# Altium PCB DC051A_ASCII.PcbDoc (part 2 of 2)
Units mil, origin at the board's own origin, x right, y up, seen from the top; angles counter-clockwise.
Board outline 3200 x 2600 mil, 4 copper layers (L1-TOP, L2-GND, L3-POWER, L4-BOTTOM), stack 58.217 mil thick; 95 components, 55 nets, 249 pads, 164 vias.
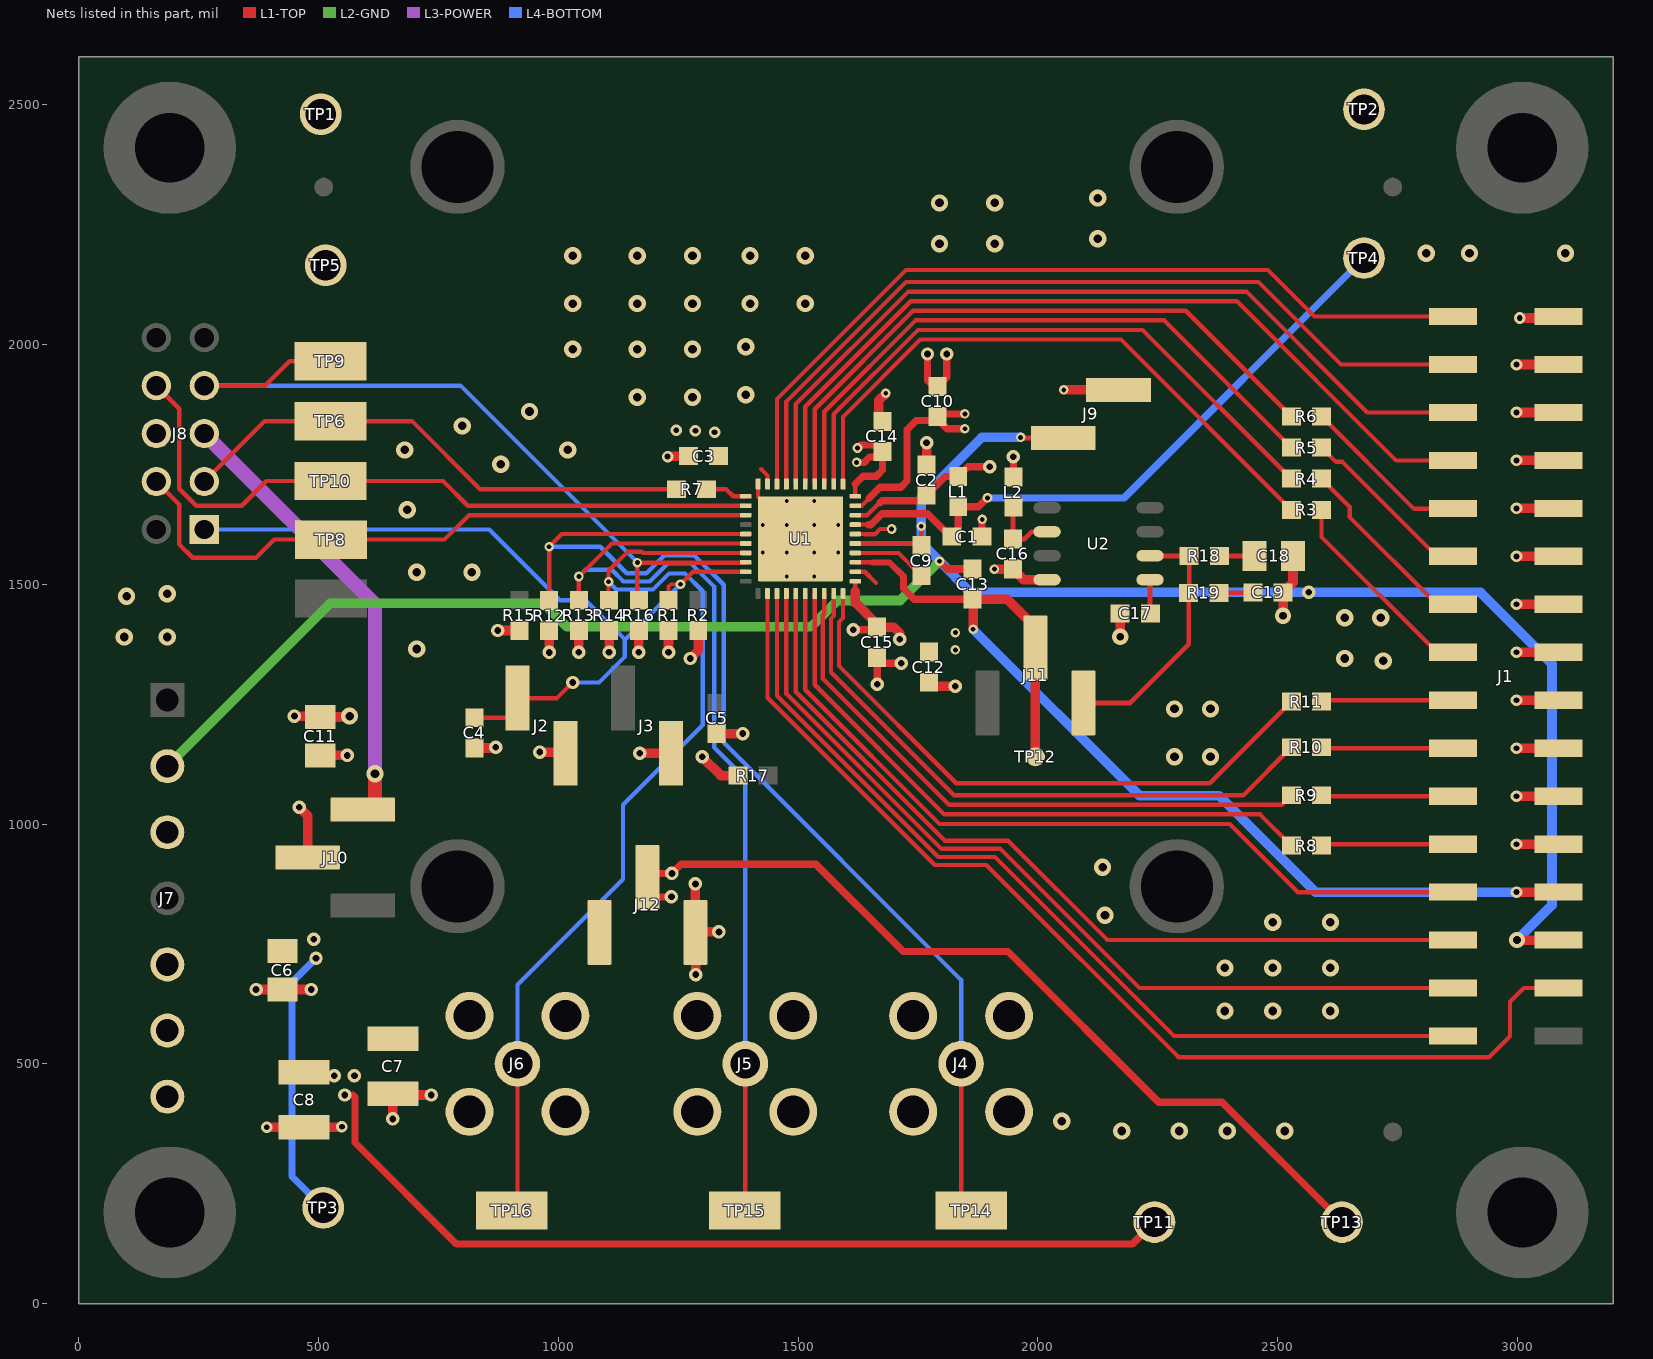
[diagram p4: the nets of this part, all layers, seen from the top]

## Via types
v1: diameter 36, hole 18, L1-TOP to L4-BOTTOM, tented both sides, 64 vias
v2: diameter 28, hole 14, L1-TOP to L4-BOTTOM, tented both sides, 41 vias
v3: diameter 20, hole 10, L1-TOP to L4-BOTTOM, tented both sides, 25 vias
v4: diameter 24, hole 12, L1-TOP to L4-BOTTOM, tented both sides, 19 vias
v5: diameter 19.68, hole 7.87, L1-TOP to L4-BOTTOM, 12 vias
v6: diameter 34, hole 16, L1-TOP to L4-BOTTOM, 3 vias

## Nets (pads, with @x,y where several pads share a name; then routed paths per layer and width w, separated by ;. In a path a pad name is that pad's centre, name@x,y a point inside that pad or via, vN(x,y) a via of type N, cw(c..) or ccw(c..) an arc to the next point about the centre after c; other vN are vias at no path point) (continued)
GND: C1.2 C2.2 C3.2 C4.2 C5.2 C6.2 C7.2 C8.2 C10.2 C11.2 C12.2 C14.2 C15.2 C16.2 C17.2 C18.2 C19.2 J1.9 J1.11 J1.13 J1.15 J1.17 J1.19 J1.21 J1.23 J1.25 J1.27 J1.29 J1.31 J2.1 J3.1 J4.2 J4.3 J4.4 J4.5 J5.2 J5.3 J5.4 J5.5 J6.2 J6.3 J6.4 J6.5 J7.3 J8.6 J9.1 J12.1 TP1.1 TP2.1 U1.10 U1.36 U1.41@1505.28,1594.7 U2.4 | length 3247.9
  L1-TOP w9: U1.10@1416.69,1708.88 1416.69,1683.28 U1.41@1505.28,1594.7 ; U1.36@1619.45,1604.54 1638.39,1604.54 1638.77,1604.17 1660.27,1604.17 1671.11,1615 v3(1695,1615)
  L1-TOP w10: J1.31@3054,2058 J1.31@3086,2058
  L1-TOP w15: v2(1665,1291.5) 1665,1339 1669,1335 v2(1715,1335) ; v2(1770,1980) 1770,1925 1782.5,1912.5 1786.75,1916.75 1791,1921 1800,1921 1810,1931 v2(1810,1980) ; C1.2@1883.5,1599 v3@1883.5,1637.5
  L1-TOP w20: v2(370,655) C6.2@425,655 v2(485,655) ; v4(392.09,367.91) C8.2@470,367.91 547.91,367.91 v4(548.96,368.96) ; v2(450,1225) 501,1225 C11.2@503,1223 ; C11.2@504,1223 563,1223 v1(565,1225) ; v2(655,385) C7.2@655,437.91 657.91,435 v2(735,435) ; C4.2@825,1158.5 873.5,1158.5 872.01,1160 v2(870,1160) ; v2@960,1150 v2(961.5,1150) J2.1@1030,1150 ; v2(1170,1147.52) J3.1@1235,1147.52 ; v4(1228,1766) 1229,1767 C3.2@1271.5,1767 ; v2(1286,875) J12.1@1286,774.02 ; v2(1287,686) 1287,710 1277,720 1286,729 J12.1@1286,774.02 ; C5.2@1322.5,1185 C5.2@1330,1185 ; C5.2@1330,1188.5 v2(1385,1188.5) ; v2(1335,775) 1287,775 J12.1@1286,774.02 ; C14.2@1668,1849 1668,1883 v3(1683,1898) ; C2.2@1768,1748.5 v2(1768,1795) ; C12.2@1773,1287 v2(1828,1287) ; v3(1909.5,1531.5) C16.2@1948,1531.5 1970.16,1509.34 U2.4@2019.36,1509.34 ; v3(2054,1905) J9.1@2168,1905 ; v6(2171.5,1390.5) C17.2@2171.5,1439 ; v6(2511,1434) 2511.5,1434.5 C19.2@2511.5,1483 2532,1503.5 C18.2@2532,1559 ; v4(2998,958) J1.9@3086,958 ; v4(2998,1058) J1.11@3086,1058 ; v4(2998,1158) J1.13@3086,1158 ; v4(2998,1258) J1.15@3086,1258 ; v4(2998,1358) J1.17@3086,1358 ; v4(2998,1458) J1.19@3086,1458 ; v4(2998,1558) J1.21@3086,1558 ; v4(2998,1658) J1.23@3086,1658 ; v4(2998,1758) J1.25@3086,1758 ; v4(2998,1858) J1.27@3086,1858 ; v4(2998,1958) J1.29@3086,1958 ; v4(3005,2055) J1.31@3093,2055
  other v1: 2175,360 2295,360 2395,360 2515,360 2050,380 2390,610 2490,610 2610,610 2390,700 2490,700 2610,700 2490,795 2610,795 2140,810 2135,910 2285,1140 2360,1140 2285,1240 2360,1240 2720,1340 2640,1345 705,1365 95,1390 185,1390 2640,1430 2715,1430 100,1475 185,1480 705,1525 820,1525 685,1655 880,1750 680,1780 1020,1780 800,1830 940,1860 1165,1890 1280,1890 1391.1,1895 1030,1990 1165,1990 1280,1990 1391.1,1995 1030,2085 1165,2085 1280,2085 1400,2085 1515,2085 1030,2185 1165,2185 1280,2185 1400,2185 1515,2185 2810,2190 2900,2190 3100,2190 1795,2210 1910,2210 2125,2220 1795,2295 1910,2295 2125,2305
  other v3: 1884,1635
  other v5: 1476.54,1515.96 1534.02,1515.96 1426.54,1565.96 1476.54,1565.96 1534.02,1565.96 1584.02,1565.96 1426.54,1623.44 1476.54,1623.44 1534.02,1623.44 1584.02,1623.44 1476.54,1673.44 1534.02,1673.44
LDAC_GPIO3: J8.7 R16.2 TP9.1 U1.18 | length 1650.6
  L1-TOP w9: J8.7@262,1914 389,1914 440,1965 TP9.1@525,1965 ; R16.2@1168,1466.5 1173.49,1471.99 1165,1480.47 v3(1165,1545) 1390.62,1545 U1.18@1391.1,1545.49
  L4-BOTTOM w9: J8.7@262,1914 796,1914 v3(1165,1545)
MISO_RXD: J8.3 R7.1 TP6.1 | length 1095.5
  L1-TOP w9: J8.3@262,1714 388,1840 TP6.1@525,1840 695,1840 837,1698 R7.1@1246.5,1698
MOSI_TXD: J8.4 TP8.1 U1.13 | length 1380.4
  L1-TOP w9: J8.4@162,1714 210,1666 210,1583 238,1555 370,1555 408,1593 TP8.1@526,1593 763,1593 813.91,1643.91 U1.13@1391.1,1643.91
NetC1_1: C1.1 L1.2 TP4.1 U1.37 | length 1359.3
  L1-TOP w8: U1.37@1619.45,1624.23 1647,1624.23
  L1-TOP w15: 1647,1624.04 1652.04,1624.04 1675,1647 1770,1647 1814.25,1602.75 1816.75,1602.75 C1.1@1820.5,1599 1820.5,1603.5 1834,1617 L1.2@1834,1661.5 1876.5,1661.5 v3(1895,1680)
  L4-BOTTOM w15: v3(1895,1680) 2180,1680 TP4.1@2680,2180
NetC9_1: C9.1 U1.34 | length 157.3
  L1-TOP w9: U1.34@1619.45,1565.17 1709.33,1565.17 C9.1@1757,1517.5
NetC10_1: C10.1 C12.1 J12.2 TP13.1 U1.32 U1.39 | length 2343.4
  L1-TOP w9: U1.32@1619.45,1525.8 1639.2,1525.8 1662.5,1502.5 ; U1.39@1619.45,1663.6 1632.6,1663.6 1634.99,1665.99 1635.23,1665.99 1643.64,1674.39 1643.64,1674.64 1648,1679
  L1-TOP w15: J12.2@1186,934 J12.2@1186,888.98 1194.02,897 v2(1237,897) 1256,916 1537.15,916 1719.15,734 1938,734 2252,420 2384,420 TP13.1@2634,170 ; J12.2@1193.02,848.02 v2(1236,848.02) ; 1648,1679.35 1670.65,1702 1714,1702 1727,1715 1727,1822 1746,1841 C10.1@1791,1841 ; v3(1848,1824) 1811,1824 1794,1841 C10.1@1791,1841 ; v3(1848,1855) 1805,1855 C10.1@1791,1841
  other v3: 1828,1363 1828,1399
NetC16_1: C16.1 L2.2 U2.2 | length 143.9
  L1-TOP w10: L2.2@1949,1660.5 1948,1659.5 C16.1@1948,1594.5 1972.76,1594.5 1987.61,1609.34 U2.2@2019.36,1609.34
NetC17_1: C17.1 U2.5 | length 70.6
  L1-TOP w10: U2.5@2233.93,1509.34 2233.93,1439.56 C17.1@2234.5,1439
NetC18_1: C18.1 R18.1 | length 73.5
  L1-TOP w10: R18.1@2378.5,1559 C18.1@2452,1559
NetC19_1: C19.1 R19.1 | length 71.4
  L1-TOP w10: R19.1@2377.5,1482 2447.5,1482 C19.1@2448.5,1483
NetJ1_3: J1.3 U1.22 | length 2279.1
  L1-TOP w9: U1.22@1436.38,1480.53 1436.38,1263.17 1785.17,914.38 1892.62,914.38 2293,514 2941,514 2984.5,557.5 2984.5,629.5 3013,658 J1.3@3086,658
NetJ4_1: J4.1 R12.2 TP14.1 U1.15 | length 2488.7
  L1-TOP w8: R12.2@981,1484 R12.2@986,1479
  L1-TOP w9: R12.2@981,1466 981,1484 v3(981,1578) 1007.54,1604.54 U1.15@1391.1,1604.54 ; J4.1@1840,500 1840,220 TP14.1@1866,194
  L4-BOTTOM w9: v3(981,1578) 1087.51,1578 1142.88,1522.63 1183.73,1522.63 1221.23,1560.12 1283.74,1560.12 1345,1498.86 1345,1170 1840,675 J4.1@1840,500
NetJ5_1: J5.1 R13.2 TP15.1 U1.16 | length 2087.8
  L1-TOP w9: R13.2@1043,1466.5 v3(1043,1516) 1111.86,1584.86 U1.16@1391.1,1584.86 ; TP15.1@1389,194 1389.99,194.99 J5.1@1389.99,500
  L4-BOTTOM w9: v3(1043,1516) 1057,1530 1111.64,1530 1135.89,1505.75 1190.72,1505.75 1228.22,1543.25 1276.75,1543.25 1325,1495 1325,1160 1390,1095 J5.1@1389.99,500
NetJ6_1: J6.1 R14.2 TP16.1 U1.17 | length 2062.5
  L1-TOP w8: v3(1105,1505) 1105,1473.5 1102,1470.5 R14.2@1106,1466.5
  L1-TOP w9: TP16.1@888,194 915,221 J6.1@915,500 ; v3(1105,1505) 1105,1527.99 1144.38,1567.37 1174.27,1567.37 1176.47,1565.17 U1.17@1391.1,1565.17
  L4-BOTTOM w9: J6.1@915,500 915,665 1135,885 1135,1040 1301.37,1206.37 1301.37,1485.27 1264.27,1522.37 1231.21,1522.37 1197.71,1488.88 1121.12,1488.88 v3(1105,1505)
NetJ11_1: J11.1 R18.2 R19.2 U2.6 | length 551.6
  L1-TOP w10: J11.1@2095,1252.52 2192.5,1252.5 2314.5,1374.5 R19.2@2314.5,1482 2315.5,1483 R18.2@2315.5,1559 2219.34,1559 U2.6@2219,1559.34
NetR3_1: R3.1 U1.1 | length 1288.4
  L1-TOP w9: U1.1@1593.86,1708.88 1593.86,1848.86 1755,2010 2173.5,2010 R3.1@2528.5,1655
NetR4_1: R4.1 U1.2 | length 1300.9
  L1-TOP w9: U1.2@1574.17,1708.88 1574.18,1854.18 1750,2030 2218.5,2030 R4.1@2528.5,1720
NetR5_1: R5.1 U1.3 | length 1313.3
  L1-TOP w9: U1.3@1554.49,1708.88 1554.49,1859.49 1745,2050 2263.5,2050 R5.1@2528.5,1785
NetR6_1: R6.1 U1.4 | length 1325.8
  L1-TOP w9: U1.4@1534.8,1708.88 1534.81,1864.81 1740,2070 2308.5,2070 R6.1@2528.5,1850
NetR7_2: R7.2 U1.11 | length 87.7
  L1-TOP w9: R7.2@1309.5,1698 1350,1698 1364.72,1683.28 U1.11@1391.1,1683.28
NetR8_1: R8.1 U1.27 | length 1322.9
  L1-TOP w9: U1.27@1534.8,1480.53 1534.81,1290.19 1805,1020 2463.5,1020 R8.1@2528.5,955
NetR9_1: R9.1 U1.28 | length 1272.6
  L1-TOP w9: U1.28@1554.49,1480.53 1554.49,1437.86 1551.68,1435.05 1551.68,1303.32 1815,1040 2508.5,1040 R9.1@2528.5,1060
NetR10_1: R10.1 U1.29 | length 1274
  L1-TOP w9: U1.29@1574.17,1480.53 1574.18,1433.68 1568.55,1428.06 1568.55,1316.45 1825,1060 2428.5,1060 R10.1@2528.5,1160
NetR11_1: R11.1 U1.30 | length 1269.2
  L1-TOP w9: U1.30@1593.86,1480.53 1593.86,1429.5 1585.43,1421.07 1585.43,1329.57 1830,1085 2358.5,1085 R11.1@2528.5,1255
OUT0: J1.18 R3.2 | length 430.6
  L1-TOP w9: R3.2@2591.5,1655 2591.5,1598.5 2832,1358 J1.18@2866,1358
OUT1: J1.20 R4.2 | length 395.6
  L1-TOP w9: R4.2@2591.5,1720 2650,1661.5 2650,1640 2832,1458 J1.20@2866,1458
OUT2: J1.22 R5.2 | length 368.5
  L1-TOP w9: R5.2@2591.5,1785 2621.5,1755 2635,1755 2832,1558 J1.22@2866,1558
OUT3: J1.24 R6.2 | length 354.9
  L1-TOP w9: R6.2@2591.5,1850 2784.5,1657 2865,1657 J1.24@2866,1658
OUT4: J1.26 U1.5 | length 1740.7
  L1-TOP w9: U1.5@1515.12,1708.88 1515.12,1870.12 1735,2090 2415,2090 2747,1758 J1.26@2866,1758
OUT5: J1.28 U1.6 | length 1738.7
  L1-TOP w9: U1.6@1495.43,1708.88 1495.43,1875.43 1730,2110 2435,2110 2687,1858 J1.28@2866,1858
OUT6: J1.30 U1.7 | length 1736.6
  L1-TOP w9: U1.7@1475.75,1708.87 1475.75,1880.75 1725,2130 2460,2130 2632,1958 J1.30@2866,1958
OUT7: J1.32 U1.8 | length 1738.7
  L1-TOP w9: U1.8@1456.06,1708.88 1456.06,1886.06 1725,2155 2480,2155 2577,2058 J1.32@2866,2058
OUT8: J1.2 U1.23 | length 1916.9
  L1-TOP w9: U1.23@1456.06,1480.53 1456.06,1267.34 1792.16,931.25 1910.75,931.25 2284,558 J1.2@2866,558
OUT9: J1.4 U1.24 | length 1853.4
  L1-TOP w9: U1.24@1475.75,1480.53 1475.75,1271.52 1799.15,948.13 1921.87,948.13 2212,658 J1.4@2866,658
OUT10: J1.6 U1.25 | length 1789.8
  L1-TOP w9: U1.25@1495.43,1480.53 1495.43,1275.7 1806.14,965 1938,965 2145,758 J1.6@2866,758
OUT11: J1.8 U1.26 | length 1726.3
  L1-TOP w9: U1.26@1515.12,1480.53 1515.12,1279.88 1795,1000 2400,1000 2542,858 J1.8@2866,858
OUT12: J1.10 R8.2 | length 275.7
  L1-TOP w9: R8.2@2591.5,955 2594.5,958 J1.10@2866,958
OUT13: J1.12 R9.2 | length 275.3
  L1-TOP w9: R9.2@2591.5,1060 2593.5,1058 J1.12@2866,1058
OUT14: J1.14 R10.2 | length 275.3
  L1-TOP w9: R10.2@2591.5,1160 2593.5,1158 J1.14@2866,1158
OUT15: J1.16 R11.2 | length 275.7
  L1-TOP w9: R11.2@2591.5,1255 2594.5,1258 J1.16@2866,1258
REFGND: C9.2 C13.2 J1.5 J7.2 J9.2 U1.35 | length 4642.3
  L1-TOP w10: U1.35@1619.45,1584.86 1752.64,1584.86 C9.2@1757,1580.5 v3(1757,1621) ; v3(1964,1806) 1965,1805 J9.2@2053.04,1805
  L1-TOP w16: v3(1795,1548) 1811.5,1531.5 C13.2@1864,1531.5
  L1-TOP w20: J7.2@185,1120.59 J7.2@187.59,1118 ; v6(2999,758) J1.5@3086,758
  L2-GND w20: J7.2@185,1120.59 524.41,1460 969,1460 1018,1411 1527,1411 1582,1466 1713,1466 v3(1795,1548)
  L4-BOTTOM w20: v3(1964,1806) 1883,1806 1757,1680 v3(1757,1621) 1757,1586 v3(1795,1548) 1860,1483 v2(2565,1483) 2923,1483 3072,1334 3072,831 v6(2999,758)
RST_GPIO9: C4.1 J2.2 J8.1 R1.1 U1.19 | length 1764.7
  L1-TOP w8: R1.1@1230,1466.5 1230,1494.95 1235.05,1500 v3(1255,1500)
  L1-TOP w9: C4.1@825,1221.5 915,1221.5 J2.2@915,1262.48 997.48,1262.48 v2(1030,1295) ; v3(1255,1500) 1280.8,1525.8 U1.19@1391.1,1525.8
  L4-BOTTOM w9: J8.1@262,1614 856,1614 1003.5,1466.5 1056.92,1466.5 1139,1384.42 1139,1384 ; v2(1030,1295) 1085,1295 1139,1349 1139,1384 ; v3(1255,1500) 1139,1384
SCLK_GPIO2: J8.8 TP10.1 U1.12 | length 1473.2
  L1-TOP w9: J8.8@162,1914 210,1866 210,1699 245.4,1663.6 340,1663.6 391.4,1715 TP10.1@525,1715 760,1715 811.4,1663.6 U1.12@1391.1,1663.6
U2A_3V3: J8.5 J10.1 | length 929.7
  L1-TOP w20: J10.1@618,1032.5 J10.1@618.5,1032
  L1-TOP w30: J10.1@618,1032.5 v1(618,1105)
  L3-POWER w30: J8.5@262,1814 618,1458 v1(618,1105)
VCC: C8.1 C14.1 C15.1 J7.7 TP11.1 U1.31 U1.40 | length 2369.1
  L1-TOP w9: 1619.45,1485.55 U1.31@1619.45,1506.12 ; U1.40@1619.45,1683.28 1619.45,1708.86
  L1-TOP w15: v2(555,435) 571.85,435 576.33,430.52 576.33,335.67 788,124 2197,124 TP11.1@2243,170 ; v2(1615,1405) 1651,1405 1660.75,1414.75 C15.1@1663.5,1417.5 ; 1619.45,1708.86 1635.46,1724.87 1662.87,1724.87 1676,1738 C14.1@1676,1768 ; v3(1622,1754) 1638,1754 1649,1765 1673,1765 C14.1@1676,1768 ; v3(1624,1784) 1630,1790 1658.35,1790 1678.17,1770.17 C14.1@1676,1768
  L1-TOP w20: 1619.45,1485.55 1619.45,1461.55 C15.1@1663.5,1417.5 ; C15.1@1665,1410.5 1699.5,1410.5 1712,1398 v2(1712,1385)
  other v2: 532.99,475 575,475
VDD/VAA: C2.1 C6.1 J7.5 L1.1 L2.1 TP3.1 U1.38 | length 932.7
  L1-TOP w9: U1.38@1619.45,1643.91 1643.81,1643.91 1669.89,1670 1671,1670
  L1-TOP w15: 1670.87,1669.87 1671,1670 1675,1674 1756.5,1674 C2.1@1768,1685.5 1806.99,1724.5 L1.1@1834,1724.5 1854.5,1745 v2(1900,1745) ; L2.1@1949,1723.5 v2(1949,1766)
  L4-BOTTOM w15: v2(495,720) 445,670 445,265 TP3.1@510,200
  other v2: 490,760
VIO: C3.1 C11.1 J10.2 R1.2 R2.2 R12.1 R13.1 R14.1 R15.1 R16.1 R17.1 TP5.1 U1.9 | length 645.1
  L1-TOP w9: 1423,1740 1436.38,1726.62 U1.9@1436.38,1708.88
  L1-TOP w20: v2(460,1035) 477.5,1017.5 J10.2@477.52,930 ; C11.1@503,1144 C11.1@504,1143 v2(560,1143) ; J10.2@503.5,932 J10.2@511,939.5 ; v2(873.68,1403.5) R15.1@919,1403.5 ; v2(981,1357.68) R12.1@981,1403.01 ; v2(1043,1358.18) R13.1@1043,1403.5 ; v2(1106,1358.18) R14.1@1106,1403.5 ; v2(1168,1358.18) R16.1@1168,1403.5 ; v2(1230,1358.18) R1.2@1230,1403.5 ; v2(1275,1345) 1292,1362 R2.2@1292,1403.5 ; v2(1300,1140) 1339,1101 R17.1@1374.5,1101
  other v4: 1326,1817 1286,1820 1246,1821
Vref: C13.1 J1.7 J11.2 TP12.1 U1.33 | length 2227.2
  L1-TOP w9: U1.33@1619.45,1545.49 1655,1545.49
  L1-TOP w13: 1655,1545.49 1690.51,1545.49 1720,1516
  L1-TOP w15: 1720,1516 1720,1491 1742.5,1468.5 C13.1@1864,1468.5
  L1-TOP w20: v3(1865,1406) 1865,1467.5 C13.1@1864,1468.5 1936.5,1468.5 1995,1410 TP12.1@1995,1140 ; v4(2998,858) J1.7@3086,858
  L4-BOTTOM w20: v3(1865,1406) 2212,1059 2378,1059 2579,858 v4(2998,858)
VSS: C7.1 J7.6 J12.3 | length 1.4
  L1-TOP w20: J12.3@1086,774.02 J12.3@1087,775
pads on no net: FID1.1 FID2.1 FID3.1 H1.1 H2.1 H3.1 H4.1 H5.MH1 H5.MH2 H5.MH3 H5.MH4 LBL1.0 SH-J1.0 SH-J2.0 SH-J3.0 SH-J4.0 U1.41@1447.8,1537.22 U1.41@1447.8,1594.7 U1.41@1447.8,1652.18 U1.41@1505.28,1537.22 U1.41@1505.28,1594.7 U1.41@1505.28,1652.18 U1.41@1562.76,1537.22 U1.41@1562.76,1594.7 U1.41@1562.76,1652.18 U2.1 U2.3 U2.7 U2.8

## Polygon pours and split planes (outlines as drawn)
NetC10_1 on L1-TOP "L1-TOP_NETC10_1_P058" (solid, remove dead copper, pour order 58): 1737.84,1690.2 1736.64,1689 1681,1689 1672,1689 1649,1666 1639,1656 1613,1656 1607,1662 1607,1668 1623,1668 1675.84,1720.84 1682.02,1720.84 1730,1720.84 1735.42,1715.42 1737.84,1713
VIO on L1-TOP "L1-TOP_VIO_P052" (solid, remove dead copper, pour order 52): 1443,1692 1432,1692 1429,1695 1429,1726 1409,1746 1367.07,1746 1316,1746 1314,1748 1314,1802.7 1230,1802.7 1230,1842.61 1342.39,1842.61 1444,1741 1444,1711 1444,1693
VSS on L1-TOP "L1-TOP_VSS_P048" (solid, remove dead copper, pour order 48): 142.57,605 142.57,525 245,525 720,525 720,595 720,665 1118.69,665 1118.69,844.28 1055,844.28 1055,750 630,750 630,605
VCC on L1-TOP "L1-TOP_VCC_P050" (solid, remove dead copper, pour order 50): 137.57,455 137.57,370.8 255,370.8 255,420 550,420 592.01,420 592.01,510 470,510 415,510 400,495 137.57,495
VDD/VAA on L1-TOP "L1-TOP_VDD/VAA_P054" (solid, remove dead copper, pour order 54): 143.57,655 345,655 345,705 513.54,705 513.54,775 290,775 143.57,775
NetC10_1 on L1-TOP "L1-TOP_NETC10_1_P056" (solid, remove dead copper, pour order 56): 1692,1460.61 1740,1412.61 1740,1343 1773,1343 1845,1343 1845,1433.87 1756.77,1433.87 1754.32,1436.32 1701.84,1488.8 1701.84,1507.16 1677,1532 1644,1532 1642,1530 1639.04,1527.04 1639.04,1509.2 1639.04,1495.61 1651.81,1482.84 1674.04,1460.61 1683,1460.61
GND on L3-POWER "L3-POWER_GND_P072" (solid, remove dead copper, pour order 72): 3160.7,2257.7 2825,2257.7 2825,2550 370,2550 370,2255 35,2255 35,340 370,340 370,280 370,50 2850,50 2850,340 3160.7,340
VCC on L3-POWER "L3-POWER_VCC_P068" (solid, remove dead copper, pour order 68): 490,495 490,475 545,420 565,420 755,610 755,625 790,660 885,660 1154.58,929.58 1419.58,929.58 1725,1235 1725,1804.72 1600,1804.72 1600,1245 1345,990 1070,990 835,755 750,755
VDD/VAA on L3-POWER "L3-POWER_VDD/VAA_P066" (solid, remove dead copper, pour order 66): 490,695 515,695 667.23,847.24 667.23,902.23 775,1010 1235,1010 1335,1010 1565,1240 1565,1320 1565,1900 1905,1900 1905,1765 1885,1765 1885,1724.5 1970,1724.5 1970,1970 1391.1,1970 1391.1,1518.9 1420,1490 1420,1191.16 1313.84,1085 740,1085 430.99,775.99 430.99,754.01
VIO on L3-POWER "L3-POWER_VIO_P070" (solid, remove dead copper, pour order 70): 1345,2255 35,2255 35,2012.84 35,1005 590,1005 705.13,1120.13 1300.13,1120.13 1345,1165
NetC10_1 on L3-POWER "L3-POWER_NETC10_1_P064" (solid, remove dead copper, pour order 64): 1860,1865 1770,1865 1750,1845 1750,1210 1455,915 1216.34,915 1216.34,805 1465,805 1850.43,1190.43 1850.43,1363 1850.43,1804 1860,1813.57
GND on L2-GND "PWR Layer L3-VEE" (solid, remove dead copper, pour order 74): -1,2593 3199,2593 3199,-3 3203,-7 7,-7 -1,1 -1,2597 -5,2601
GND on L4-BOTTOM "L4-BOTTOM_GND_P060" (solid, remove dead copper, pour order 60): 3160.7,2257.7 2825,2257.7 2825,2550 370,2550 370,2255 35,2255 35,340 370,340 370,280 370,50 2850,50 2850,340 3160.7,340

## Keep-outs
Keep-Out Layer:
  text ".Layer_Name" at 655,-858.49 h60

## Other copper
L1-TOP:
  text ".Layer_Name" at 655,-858.49 h60
L3-POWER:
  text ".Layer_Name" at 680,-856 h60
L2-GND:
  text ".Layer_Name" at 680,-856 h60
L4-BOTTOM:
  text ".Layer_Name" at 655,-858.49 h60

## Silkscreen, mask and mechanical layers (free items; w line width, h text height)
Top Overlay:
  circle w7: c701,1031 r11.4
  circle w7: c1286,951 r11.4
  circle w7: c2097,1146 r11.4
  lines w6: 1715,1915 1732,1898 1732,1780.42
  text "GND" at 354,2534 h35
  text "GND" at 2493,2463 h35
  text "VAA" at 2498,2228 h60
  text "VIO" at 619,2130 h35
  text "LDACz" at 647,1935 h60
  text "MISO" at 652,1806 h60
  text "SCLK" at 631,1673 h60
  text "MOSI" at 629,1543 h60
  text "CSz" at 474,1359 h60
  text "Vref" at 1966,1005 h60
  text "'.PRJ_Number''.PCB_Rev'" at 2111,648 h60
  text "TOG2" at 838,275 h55
  text "TOG0" at 1789,272 h55
  text "TOG1" at 1319,269 h55
  text "VCC" at 2192,262 h60
  text "VSS" at 2443,148 h60
  text "VDD" at 461,75 h60
  text ".Layer_Name" at 655,-858.49 h60
Bottom Overlay:
  text ".Layer_Name" at 655,-858.49 h60
Top Paste:
  text ".Layer_Name" at 655,-858.49 h60
Bottom Paste:
  text ".Layer_Name" at 655,-858.49 h60
Top Solder:
  text ".Layer_Name" at 655,-858.49 h60
  text ".Layer_Name" at 655,-858.49 h60
Bottom Solder:
  text ".Layer_Name" at 655,-858.49 h60
Drill Guide:
  text ".Layer_Name" at 655,-858.49 h60
M1 Board Outline:
  the board outline again, w10
M2 Board Dimensions:
  rectangle: 78,-275 203,-150
  rectangle: 203,-400 578,-275
  lines w7: 78,-275 1078,-275 ; 203,-400 203,-150 ; 328,-400 328,-150 ; 578,-400 578,-150 ; 828,-400 828,-150 ; 78,-400 1078,-400 1078,-150 78,-150 78,-400
  text ".Layer_Name" at 655,-858.49 h60
M3 3D STEP Top:
  text ".Layer_Name" at 655,-858.49 h60
M4 3D STEP Bottom:
  text ".Layer_Name" at 655,-858.49 h60
M5 Assembly Top:
  lines w10: -214,-930.17 6386,-930.17 ; -214,-726.83 6388,-726.83 ; -214,-523.5 -214,-1133.5 3791,-1133.5 6388,-1133.5 6388,-523.5 -213.5,-523.5 -213.5,-1133.5 1362,-1133.5 ; 2251,-1133.5 2251,-523.5 ; 3518,-726.83 3518,-523.5 ; 4358,-726.83 4358,-523.5 ; 4980,-1140 4980,-937.17
  text "COMPONENTS MARKED 'DNP' SHOULD NOT BE POPULATED." at 1231.5,-318.5 h60
  text "ASSEMBLY VARIANT:" at 1231,-434 h60
  text ".VariantName" at 2267,-434 h60
  text "PCB VIEWED FROM TOP SIDE" at -150.5,-655.67 h60
  text "BOARD #:" at 2326,-655.67 h60
  text ".PRJ_Number" at 2871.5,-655.67 h60
  text "REV:" at 3716,-655.67 h60
  text ".PCB_Rev" at 4007.5,-655.67 h60
  text "SVN REV:" at 4554,-655.67 h60
  text ".VersionControl_RevNumber" at 5060,-655.67 h60
  text "TID #:" at 2326,-859 h60
  text ".TID" at 2871.5,-859 h60
  text "PLOT NAME =" at -150.5,-1064.34 h60
  text ".plot_File_Name" at 655,-1064.34 h60
  text "GENERATED    :" at 2328,-1064.34 h60
  text ".Print_Date" at 3197.5,-1064.34 h60
  text ".Print_Time" at 3926.5,-1064.34 h60
  text "TEXAS INSTRUMENTS" at 5191,-1064.34 h60
M6 Assembly Bottom:
  lines w10: -214.5,-727.33 6387.5,-727.33 ; -212.5,-930.67 6387.5,-930.67 ; 1193.5,-1140.5 1193.5,-937.67 ; 1815.5,-727.33 1815.5,-524 ; 2655.5,-727.33 2655.5,-524 ; 3922.5,-1134 3922.5,-524 ; 4811.5,-1134 6387,-1134 6387,-524 -214.5,-524 -214.5,-1134 2382.5,-1134 6387.5,-1134 6387.5,-524
  text "COMPONENTS MARKED 'DNP' SHOULD NOT BE POPULATED." at 6180,-318 h60
  text ".VariantName" at 5136,-434 h60
  text "ASSEMBLY VARIANT:" at 6175,-434 h60
  text ".VersionControl_RevNumber" at 1113.5,-656.17 h60
  text "SVN REV:" at 1619.5,-656.17 h60
  text ".PCB_Rev" at 2166,-656.17 h60
  text "REV:" at 2457.5,-656.17 h60
  text ".PRJ_Number" at 3302,-656.17 h60
  text "BOARD #:" at 3847.5,-656.17 h60
  text "PCB VIEWED FROM BOTTOM SIDE" at 6324,-656.17 h60
  text ".TID" at 3302,-859.5 h60
  text "TID #:" at 3847.5,-859.5 h60
  text "TEXAS INSTRUMENTS" at 982.5,-1064.84 h60
  text ".Print_Time" at 2247,-1064.84 h60
  text ".Print_Date" at 2976,-1064.84 h60
  text "GENERATED    :" at 3845.5,-1064.84 h60
  text ".plot_File_Name" at 5518.5,-1064.84 h60
  text "PLOT NAME =" at 6324,-1064.84 h60
M9 Title Sheet:
  lines w10: -413.5,1041.5 -213.5,1041.5 ; -413.5,3416.5 -213.5,3416.5 ; -413.5,5791.5 -213.5,5791.5 ; 2086.5,-1333.5 2086.5,-1133.5 ; 2086.5,7966.5 2086.5,8166.5 ; 4586.5,-1333.5 4586.5,-1133.5 ; 4586.5,7966.5 4586.5,8166.5 ; 6399,-1133.5 6399,-523.5 11381.5,-523.5 ; 7086.5,-1333.5 7086.5,-1133.5 ; 7086.5,7966.5 7086.5,8166.5 ; 9586.5,-1333.5 9586.5,-1133.5 ; 9586.5,7966.5 9586.5,8166.5 ; 11381.5,-1133.5 11381.5,-523.5 ; 11381.5,-823.5 14381.5,-823.5 ; 11381.5,-223.5 14381.5,-223.5 ; 11382.5,370.5 14382.5,370.5 ; 12086.5,-1333.5 12086.5,-1133.5 ; 12086.5,7966.5 12086.5,8166.5 ; 12886.5,-1123.5 12886.5,-523.5 ; 14381.5,-523.5 11381.5,-523.5 ; 14381.5,76.5 11381.5,76.5 ; 14386.5,66.5 14386.5,-1133.5 ; 14386.5,871 11382.5,871 11381.5,871 11381.5,370.5 11381.5,76.5 ; 14386.5,1041.5 14586.5,1041.5 ; 14386.5,3416.5 14586.5,3416.5 ; 14386.5,5791.5 14586.5,5791.5 ; 11381.5,-523.5 11381.5,76.5 ; 14386.5,-1133.5 14386.5,7966.5 -213.5,7966.5 -213.5,-1133.5 14386.5,-1133.5 ; -413.5,-1333.5 -413.5,8166.5 14586.5,8166.5 14586.5,-1333.5 -413.5,-1333.5
  text "1" at 817.84,8036.5 h70
  text "2" at 3313.5,8036.5 h70
  text "3" at 5802.84,8036.5 h70
  text "4" at 8309.51,8036.5 h70
  text "5" at 10808.5,8036.5 h70
  text "6" at 13313.5,8036.5 h70
  text "A" at -338.5,6893.5 h70
  text "A" at 14461.5,6893.5 h70
  text "B" at -338.5,4513.5 h70
  text "B" at 14461.5,4513.5 h70
  text "C" at -338.5,2138.5 h70
  text "C" at 14461.5,2138.5 h70
  text "PROJECT TITLE:" at 11421.5,277.5 h45
  text ".PRJ_Title" at 11471.5,144.17 h70
  text "DESIGNED FOR:" at 11421.5,-23.5 h45
  text ".PRJ_Customer" at 11471.5,-163.5 h70
  text "D" at -338.5,-231.5 h70
  text "D" at 14461.5,-231.5 h70
  text "FILE NAME:" at 11421.5,-323.5 h45
  text ".PCB_File_Name_No_Path" at 11471.5,-443.5 h70
  text "Texas Instruments (TI) and/or its licensors do not warrant the accuracy or completeness of this specification" at 6452,-605.34 h45
  text "ENGINEER:" at 11421.5,-613.5 h45
  text "LAYOUT BY:" at 12926.5,-613.5 h45
  text "or any information contained therein. TI and/or its licensors do not warrant that this design will meet" at 6407.01,-718 h45
  text ".PRJ_Engineer" at 11471.5,-768.49 h70
  text ".PCB_Layout" at 12977,-768.49 h70
  text "the specifications, will be suitable for your application or fit for any particular purpose, or will operate in" at 6407.01,-830.67 h45
  text ".Layer_Name" at 655,-858.49 h60
  text "ALTIUM DESIGNER VERSION:" at 12926.5,-923.5 h45
  text "an implementation. TI and/or its licensors do not warrant that the design is production worthy. You should" at 6407.01,-943.33 h45
  text "completely validate and test your design implementation to confirm the system functionality for your application." at 6452,-1056 h45
  text ".print_Scale" at 11471.5,-1056.83 h70
  text ".Application_BuildNumber" at 12977,-1056.83 h70
  text "1" at 817.84,-1263.5 h70
  text "2" at 3313.5,-1263.5 h70
  text "3" at 5802.84,-1263.5 h70
  text "4" at 8309.51,-1263.5 h70
  text "5" at 10808.5,-1263.5 h70
  text "6" at 13313.5,-1263.5 h70
M10 Fab Notes:
  drawing of 189 lines, arcs and shapes, not listed
  text "DESIGN INFORMATION" at 12460.02,6356.17 h60
  text "MIN. TRACK WIDTH:" at 11815.46,6224.05 h60
  text "8" at 12911.7,6224.05 h60
  text "MIL" at 13066.46,6224.05 h60
  text "MIN. CLEARANCE:" at 11815.46,6099.92 h60
  text "0.2" at 12851.7,6099.93 h60
  text "mm" at 13066.46,6099.92 h60
  text "MIN. VIA PAD SIZE:" at 11815.46,5975.8 h60
  text "24" at 12881.71,5975.8 h60
  text "MIL" at 13066.46,5975.8 h60
  text "0.05mm (2MIL)" at 12510.46,5845.9 h60
  text "MINIMUM ANNULAR RING" at 11486.23,5837.67 h60
  text "EXTERNAL" at 13218.46,5837.67 h60
  text "PER" at 11686.23,5727.55 h60
  text "IPC-D-275 CLASS 2 LEVEL C" at 11906.23,5727.54 h60
  text "MIL, HOLES" at 13394.46,5627.07 h60
  text "+/-" at 13002,5618.48 h60
  text "+/-" at 13856,5618.48 h60
  text "REGISTRATION TOLERANCES:" at 11486.23,5617.42 h60
  text "METAL" at 12686,5617.42 h60
  text "5" at 13262.2,5617.42 h60
  text "3" at 14095.2,5617.42 h60
  text "MIL" at 14211.46,5617.42 h60
  text "HOLE SIZE TOLERANCE (UNLESS OTHERWISE SPECIFIED):" at 11486.23,5519.1 h60
  text "+/-" at 13856,5516.23 h60
  text "3" at 14095.2,5515.17 h60
  text "MIL" at 14211.46,5515.17 h60
  text "MATERIAL:" at 11411.46,5377.52 h60
  text "FR-4 High Tg" at 12397.9,5249 h60
  text "X" at 12253.46,5241.01 h60
  text "FR-408" at 11832.46,5236.49 h60
  text "OTHER" at 13320.46,5236.49 h60
  text "62 MIL (1.6mm) +/-10%" at 12152.56,5093.46 h60
  text "X" at 12032.46,5091.01 h60
  text "THICKNESS:" at 11486.23,5085.24 h60
  text "OTHER" at 13437.46,5085.24 h60
  text "TOLERANCE:" at 11486.23,4946.92 h60
  text "X" at 12334.46,4946.92 h60
  text "ANSI IPC-6012 TYPE 3 CLASS 2" at 12512.48,4946.92 h60
  text "OTHER +/-" at 12512.46,4802.73 h60
  text "BOW & TWIST:" at 11486.23,4657.54 h60
  text "X" at 12334.46,4657.54 h60
  text "ANSI IPC-6012 TYPE 3 CLASS 2" at 12512.48,4657.54 h60
  text "OTHER +/-" at 12512.46,4510.85 h60
  text "DRILLING:" at 11411.46,4380.23 h60
  text "NC_DRILL FILES" at 13172.46,4275.04 h60
  text "REFERENCE:" at 11486.23,4271.1 h60
  text "X" at 12143.46,4271.01 h60
  text "AS SHOWN" at 12321.46,4271.1 h60
  text "X" at 13044.46,4271.1 h60
  text "OTHER" at 13470.46,4128.85 h60
  text "PTH COPPER THICKNESS:" at 11485.91,4125.32 h60
  text "X" at 12625.14,4125.32 h60
  text "20-30 um" at 12753.14,4125.32 h60
  text "BOARD FINISH:" at 11411.46,3977.73 h60
  text "SILKSCREEN:" at 11566.68,3867.6 h60
  text "X" at 12524.46,3867.6 h60
  text "TOP" at 12641.46,3867.6 h60
  text "X" at 13034.46,3867.6 h60
  text "BOTTOM" at 13152.46,3867.6 h60
  text "SILKSCREEN COLOR:" at 11566.68,3712.41 h60
  text "X" at 12523.46,3712.41 h60
  text "WHITE" at 12641.46,3712.41 h60
  text "OTHER" at 13152.46,3712.41 h60
  text "GREEN" at 12772.46,3568.96 h60
  text "OTHER" at 13390.46,3568.96 h60
  text "X" at 12651,3568 h60
  text "SOLDER RESIST COLOR:" at 11566.68,3562.1 h60
  text "X" at 12654.46,3414.71 h60
  text "MATTE" at 12772.46,3414.71 h60
  text "SEMI-GLOSS" at 13390,3414.07 h60
  text "IMMERSION GOLD (ENIG)" at 12472.46,3241.94 h60
  text "ENEPIG" at 13810,3234.72 h60
  text "SURFACE FINISH:" at 11411.46,3233.72 h60
  text "X" at 12294.46,3233.72 h60
  text "IMM. TIN/SILVER OR EQUIV" at 11741,3096.4 h60
  text "OTHER" at 13172.46,3092.47 h60
  text "ARRAY/PANEL:" at 11411.46,2937.09 h60
  text "CUT AND TRIM PER M1 BOARD OUTLINE" at 12472.46,2928.87 h60
  text "N.C. ROUTE" at 12472.46,2792.9 h60
  text "X" at 13160.46,2792.9 h60
  text "V. SCORE" at 13338.46,2792.9 h60
  text "CERTIFICATION:" at 11411.46,2663.77 h60
  text "MATERIALS AND WORKMANSHIP FOR ALL PCBS" at 12136.46,2663.77 h60
  text "TO MEET OR EXCEED THE REQUIREMENTS OF:" at 12136.46,2569.71 h60
  text "X" at 11773.97,2441.08 h60
  text "ANSI IPC-A-600F CLASS ->" at 11901.96,2441.08 h60
  text "X" at 13549.97,2441.08 h60
  text "2" at 13659.96,2441.08 h60
  text "1" at 13344.96,2439.58 h60
  text "3" at 14013.96,2439.58 h60
  text "X" at 12585.97,2293.39 h60
  text "RoHS" at 12713.96,2293.39 h60
  text "OTHER" at 13358.36,2293.39 h60
  text "PER ORDER" at 13755.42,2293.39 h60
  text "ALL BOARDS MUST MEET OR EXCEED UL94-V0 REQUIREMENTS." at 11439,2139.57 h60
  text "PCB MUST BEAR THE UL94V-0 UL REGISTERED MATERIAL ID NUMBER" at 11439,2023.5 h60
  text "ADDITIONAL REQUIREMENTS:" at 11411.46,1854.08 h60
  text "MICROSECTION:" at 11486.23,1746.95 h60
  text "YES" at 12391.96,1746.95 h60
  text "REQUIRED" at 13253.46,1602.62 h60
  text "BARE BOARD ELEC. TEST:" at 11486.23,1599.76 h60
  text "NONE" at 12791.96,1599.76 h60
  text "X" at 13135.46,1599.76 h60
  text "PER ORDER" at 13845.46,1599.76 h60
  text "XX MIL VIAS REQUIRE NON-CONDUCTIVE FILL AND PLANARIZE" at 11654.38,1394.82 h59
  text "XX MIL VIAS REQUIRE CONDUCTIVE FILL AND PLANARIZE" at 11662.38,1290.84 h60
  text "OUTER XX MIL VIAS REQUIRE 50 OHM SINGLE-ENDED IMPEDANCE" at 11661.39,1127.46 h58
  text "LAYER 2 & 3 (INNER LAYERS) XX MIL WIDE, XX MIL SPACE / TRACES REQUIRE 100 OHM DIFFERENTIAL IMPEDANCE" at 11653.39,891.74 h60
  text ".Layer_Name" at 655,-858.49 h60
M11 Gerber Information:
  lines w10: -214,-930.17 6386,-930.17 ; -214,-726.83 6388,-726.83 ; -214,-523.5 -214,-1133.5 3791,-1133.5 6388,-1133.5 6388,-523.5 -213.5,-523.5 -213.5,-1133.5 1362,-1133.5 ; 2251,-1133.5 2251,-523.5 ; 3518,-726.83 3518,-523.5 ; 4358,-726.83 4358,-523.5 ; 4980,-1140 4980,-937.17
  text "ALL ARTWORK VIEWED FROM TOP SIDE" at -150.5,-655.67 h60
  text "BOARD #:" at 2326,-655.67 h60
  text ".PRJ_Number" at 2871.5,-655.67 h60
  text "REV:" at 3716,-655.67 h60
  text ".PCB_Rev" at 4007.5,-655.67 h60
  text "SVN REV:" at 4554,-655.67 h60
  text ".VersionControl_RevNumber" at 5060,-655.67 h60
  text "LAYER NAME =" at -150.5,-858.49 h60
  text "TID #:" at 2326,-859 h60
  text ".TID" at 2871.5,-859 h60
  text "PLOT NAME =" at -150.5,-1064.34 h60
  text ".plot_File_Name" at 655,-1064.34 h60
  text "GENERATED    :" at 2328,-1064.34 h60
  text ".Print_Date" at 3197.5,-1064.34 h60
  text ".Print_Time" at 3926.5,-1064.34 h60
  text "TEXAS INSTRUMENTS" at 5191,-1064.34 h60
M12 Stackup:
  drawing of 295 lines, arcs and shapes, not listed
  text "Layer" at 6490.5,7564 h60
  text "Name" at 6900.41,7564 h60
  text "Material" at 7830.16,7564 h60
  text "Thickness" at 8689.92,7564 h60
  text "Constant" at 9339.76,7564 h60
  text "Board Layer Stack" at 9909.62,7564 h60
  text "1" at 6490.5,7444 h60
  text "Top Overlay" at 6900.41,7444 h60
  text "2" at 6490.5,7324 h60
  text "Top Solder" at 6900.41,7324 h60
  text "Solder Resist" at 7830.16,7324 h60
  text "0.40mil" at 8689.92,7324 h60
  text "3.5" at 9339.76,7324 h60
  text "3" at 6490.5,7204 h60
  text "L1-TOP" at 6900.41,7204 h60
  text "Copper" at 7830.16,7204 h60
  text "1.40mil" at 8689.92,7204 h60
  text "4" at 6490.5,7084 h60
  text "Dielectric1" at 6900.41,7084 h60
  text "FR-406" at 7830.16,7084 h60
  text "10.00mil" at 8689.92,7084 h60
  text "4.6" at 9339.76,7084 h60
  text "5" at 6490.5,6964 h60
  text "L2-GND" at 6900.41,6964 h60
  text "Copper" at 7830.16,6964 h60
  text "1.42mil" at 8689.92,6964 h60
  text "6" at 6490.5,6844 h60
  text "Dielectric2" at 6900.41,6844 h60
  text "FR-4" at 7830.16,6844 h60
  text "32.60mil" at 8689.92,6844 h60
  text "4.8" at 9339.76,6844 h60
  text "7" at 6490.5,6724 h60
  text "L3-POWER" at 6900.41,6724 h60
  text "Copper" at 7830.16,6724 h60
  text "1.40mil" at 8689.92,6724 h60
  text "8" at 6490.5,6604 h60
  text "Dielectric3" at 6900.41,6604 h60
  text "FR-406" at 7830.16,6604 h60
  text "10.00mil" at 8689.92,6604 h60
  text "4.6" at 9339.76,6604 h60
  text "9" at 6490.5,6484 h60
  text "L4-BOTTOM" at 6900.41,6484 h60
  text "Copper" at 7830.16,6484 h60
  text "1.40mil" at 8689.92,6484 h60
  text "10" at 6490.5,6364 h60
  text "Bottom Solder" at 6900.41,6364 h60
  text "Solder Resist" at 7830.16,6364 h60
  text "0.40mil" at 8689.92,6364 h60
  text "3.5" at 9339.76,6364 h60
  text "11" at 6490.5,6244 h60
  text "Bottom Overlay" at 6900.41,6244 h60
  text ".Layer_Name" at 655,-858.49 h60
M13 Component Bodies Top:
  text ".Layer_Name" at 655,-858.49 h60
M14 Component Bodies Bottom:
  text ".Layer_Name" at 655,-858.49 h60
M15 Courtyards Top:
  text ".Layer_Name" at 655,-858.49 h60
M16 Courtyards Bottom:
  text ".Layer_Name" at 655,-858.49 h60
Drill Drawing:
  circle w10: c6167.62,2722.83 r20
  circle w10: c6167.62,2722.83 r33.33
  lines w10: 6134.29,1039.5 6167.62,1056.17 6200.96,1039.5 6184.29,1072.83 6200.96,1106.17 6167.62,1089.5 6134.29,1106.17 6150.96,1072.83 6134.29,1039.5 ; 6134.29,1206.17 6150.96,1206.17 6167.62,1189.5 6184.29,1206.17 6200.96,1206.17 6184.29,1222.83 6200.96,1239.5 6184.29,1239.5 6167.62,1256.17 6150.96,1239.5 6134.29,1239.5 6150.96,1222.83 6134.29,1206.17 ; 6134.29,1356.17 6150.96,1356.17 6167.62,1339.5 6184.29,1356.17 6200.96,1356.17 6184.29,1372.83 6200.96,1389.5 6184.29,1389.5 6167.62,1406.17 6150.96,1389.5 6134.29,1389.5 6150.96,1372.83 6134.29,1356.17 ; 6134.29,1506.17 6150.96,1506.17 6150.96,1489.5 6184.29,1489.5 6184.29,1506.17 6200.96,1506.17 6200.96,1539.5 6184.29,1539.5 6184.29,1556.17 6150.96,1556.17 6150.96,1539.5 6134.29,1539.5 6134.29,1506.17 ; 6134.29,1639.5 6200.96,1639.5 6200.96,1706.17 6134.29,1706.17 6134.29,1639.5 ; 6134.29,1856.17 6200.96,1856.17 6167.62,1789.5 6134.29,1856.17 ; 6134.29,1956.17 6150.96,1956.17 6150.96,1939.5 6184.29,1939.5 6184.29,1956.17 6200.96,1956.17 6200.96,1989.5 6184.29,1989.5 6184.29,2006.17 6150.96,2006.17 6150.96,1989.5 6134.29,1989.5 6134.29,1956.17 ; 6134.29,2089.5 6167.62,2106.17 6200.96,2089.5 6184.29,2122.83 6200.96,2156.17 6167.62,2139.5 6134.29,2156.17 6150.96,2122.83 6134.29,2089.5 ; 6134.29,2272.83 6167.62,2239.5 6200.96,2272.83 6167.62,2306.17 6134.29,2272.83 ; 6134.29,2389.5 6134.29,2406.17 6150.96,2422.83 6134.29,2439.5 6134.29,2456.17 6150.96,2456.17 6167.62,2439.5 6184.29,2456.17 6200.96,2456.17 6200.96,2439.5 6184.29,2422.83 6200.96,2406.17 6200.96,2389.5 6184.29,2389.5 6167.62,2406.17 6150.96,2389.5 6134.29,2389.5 ; 6134.29,2606.17 6200.96,2606.17 6167.62,2539.5 6134.29,2606.17 ; 6134.29,2839.5 6200.96,2839.5 6200.96,2906.17 6134.29,2906.17 6134.29,2839.5 ; 6147.62,1052.83 6167.62,1062.83 6187.62,1052.83 6177.62,1072.83 6187.62,1092.83 6167.62,1082.83 6147.62,1092.83 6157.62,1072.83 6147.62,1052.83 ; 6147.62,1212.83 6157.62,1212.83 6167.62,1202.83 6177.62,1212.83 6187.62,1212.83 6177.62,1222.83 6187.62,1232.83 6177.62,1232.83 6167.62,1242.83 6157.62,1232.83 6147.62,1232.83 6157.62,1222.83 6147.62,1212.83 ; 6147.62,1512.83 6157.62,1512.83 6157.62,1502.83 6177.62,1502.83 6177.62,1512.83 6187.62,1512.83 6187.62,1532.83 6177.62,1532.83 6177.62,1542.83 6157.62,1542.83 6157.62,1532.83 6147.62,1532.83 6147.62,1512.83 ; 6147.62,1652.83 6187.62,1652.83 6187.62,1692.83 6147.62,1692.83 6147.62,1652.83 ; 6147.62,1842.83 6187.62,1842.83 6167.62,1802.83 6147.62,1842.83
  lines w15: 6074.5,994.5 8905.76,994.5 ; 6074.5,2944.5 8905.76,2944.5 ; 6625.38,844.5 6625.38,3094.5 ; 7205.22,844.5 7205.22,3094.5 ; 8354.89,844.5 8354.89,3094.5 ; 6074.5,844.5 8905.76,844.5 8905.76,3094.5 6074.5,3094.5 6074.5,844.5
  text "Symbol" at 6164.5,2989.5 h72
  text "Count" at 6670.38,2989.5 h72
  text "Hole Size" at 7250.22,2989.5 h72
  text "Plated" at 8399.89,2989.5 h72
  text "3" at 6670.38,2839.5 h60
  text "16.00mil (0.406mm)" at 7250.22,2839.5 h60
  text "PTH" at 8399.89,2839.5 h60
  text "3" at 6670.38,2689.5 h60
  text "62.00mil (1.575mm)" at 7250.22,2689.5 h60
  text "PTH" at 8399.89,2689.5 h60
  text "4" at 6670.38,2539.5 h60
  text "145.67mil (3.700mm)" at 7250.22,2539.5 h60
  text "PTH" at 8399.89,2539.5 h60
  text "4" at 6670.38,2389.5 h60
  text "150.00mil (3.810mm)" at 7250.22,2389.5 h60
  text "PTH" at 8399.89,2389.5 h60
  text "7" at 6670.38,2239.5 h60
  text "47.24mil (1.200mm)" at 7250.22,2239.5 h60
  text "PTH" at 8399.89,2239.5 h60
  text "7" at 6670.38,2089.5 h60
  text "63.00mil (1.600mm)" at 7250.22,2089.5 h60
  text "PTH" at 8399.89,2089.5 h60
  text "10" at 6670.38,1939.5 h60
  text "40.16mil (1.020mm)" at 7250.22,1939.5 h60
  text "PTH" at 8399.89,1939.5 h60
  text "12" at 6670.38,1789.5 h60
  text "7.87mil (0.200mm)" at 7250.22,1789.5 h60
  text "PTH" at 8399.89,1789.5 h60
  text "12" at 6670.38,1639.5 h60
  text "67.00mil (1.702mm)" at 7250.22,1639.5 h60
  text "PTH" at 8399.89,1639.5 h60
  text "19" at 6670.38,1489.5 h60
  text "12.00mil (0.305mm)" at 7250.22,1489.5 h60
  text "PTH" at 8399.89,1489.5 h60
  text "25" at 6670.38,1339.5 h60
  text "10.00mil (0.254mm)" at 7250.22,1339.5 h60
  text "PTH" at 8399.89,1339.5 h60
  text "41" at 6670.38,1189.5 h60
  text "14.00mil (0.356mm)" at 7250.22,1189.5 h60
  text "PTH" at 8399.89,1189.5 h60
  text "64" at 6670.38,1039.5 h60
  text "18.00mil (0.457mm)" at 7250.22,1039.5 h60
  text "PTH" at 8399.89,1039.5 h60
  text "211 Total" at 6670.38,889.5 h60
  text ".Layer_Name" at 655,-858.49 h60
M17 Embedded Cavity:
  text ".Layer_Name" at 655,-858.49 h60
M18 Embedded Assembly:
  text ".Layer_Name" at 655,-858.49 h60
M19 Embedded Keepout:
  text ".Layer_Name" at 655,-858.49 h60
